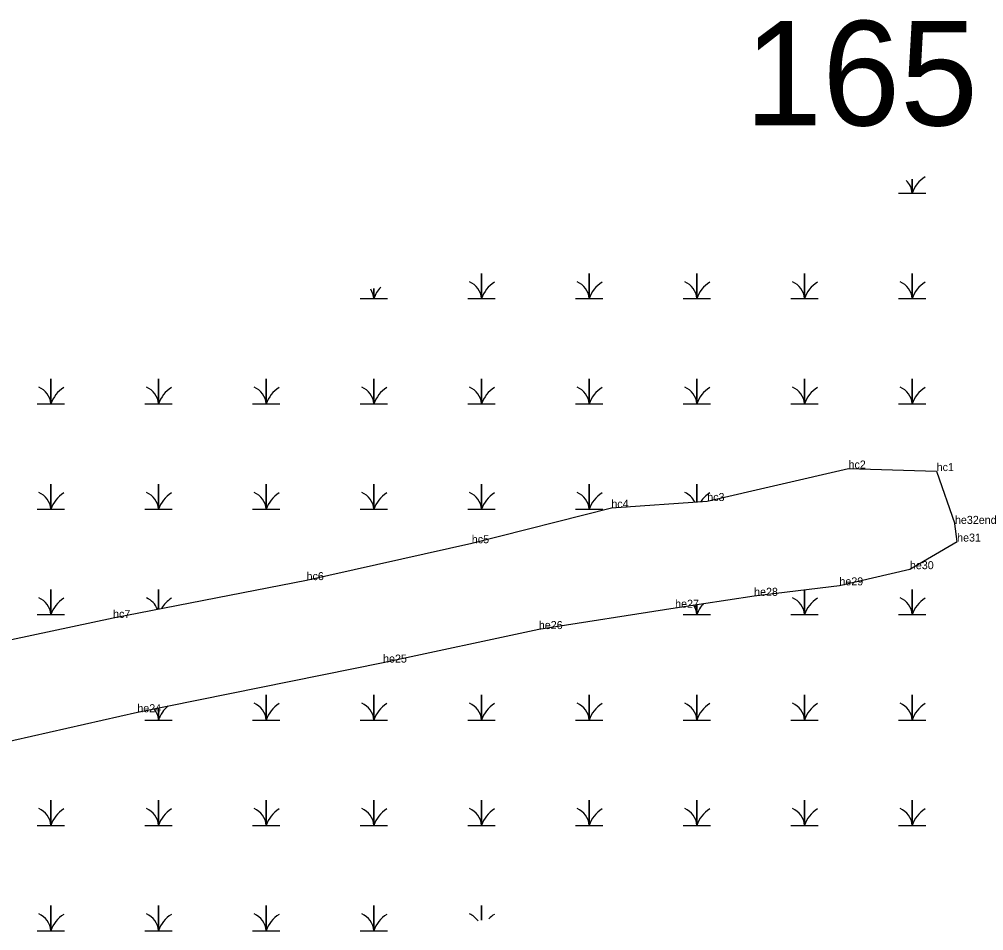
# Model space of a CAD drawing. Extents: x 2072529 to 2268796, y 436423 to 470406.
# Drawn here: x 2185430 to 2186032, y 453067 to 453636 of the extents above; entities that cross this region are included whole.
import ezdxf

# ---------------------------------------------------------------- set-up
doc = ezdxf.new("R2010")
doc.units = 0
for name, color, linetype in [('Default', 7, 'Continuous'), ('Exist Environmental Wetland Boundary', 7, 'Continuous'), ('Exist Environmental Wetland Boundary Cogo Comment', 7, 'Continuous'), ('Exist Hydro Swamp or Marsh', 7, 'Continuous'), ('Old_Level_20', 7, 'Continuous')]:
    doc.layers.add(name, color=color, linetype=linetype)

msp = doc.modelspace()

# ---------------------------------------------------------------- linework, layer by layer
at = {"layer": 'Exist Environmental Wetland Boundary'}
for points in [[(2185035.54, 453189.27), (2185047.47, 453170.42), (2185087.53, 453177.63), (2185090.05, 453198.25), (2185098.16, 453236.27), (2185126.21, 453250.87), (2185159.4, 453243.51), (2185177.54, 453239.84), (2185246.58, 453215.74), (2185332.93, 453229.41), (2185488.36, 453262.36), (2185609.23, 453285.97), (2185712.44, 453309.01), (2185799.6, 453331.13), (2185859.51, 453335.36), (2185947.74, 453355.65), (2186002.8, 453354.08), (2186014.23, 453321.09)], [(2185404.06, 453181.06), (2185503.52, 453203.47), (2185657.01, 453234.47), (2185754.31, 453255.41), (2185839.43, 453268.74), (2185888.76, 453276.18), (2185942.05, 453282.7), (2185986.08, 453292.81), (2186015.58, 453310.05), (2186014.23, 453321.09)]]:
    msp.add_lwpolyline(points, dxfattribs=at)
at = {"layer": 'Exist Hydro Swamp or Marsh'}
for points in [[(2185978.92, 453527.61), (2185987.52, 453527.61), (2185987.52, 453536.43)], [(2185987.52, 453536.43), (2185987.52, 453527.61), (2185996.12, 453527.61)], [(2185709.92, 453461.81), (2185718.52, 453461.81), (2185718.52, 453477.59), (2185718.52, 453461.81), (2185727.12, 453461.81)], [(2185777.17, 453461.81), (2185785.77, 453461.81), (2185785.77, 453477.59), (2185785.77, 453461.81), (2185794.37, 453461.81)], [(2185844.42, 453461.81), (2185853.02, 453461.81), (2185853.02, 453477.59), (2185853.02, 453461.81), (2185861.62, 453461.81)], [(2185911.67, 453461.81), (2185920.27, 453461.81), (2185920.27, 453477.59), (2185920.27, 453461.81), (2185928.87, 453461.81)], [(2185978.92, 453461.81), (2185987.52, 453461.81), (2185987.52, 453477.59), (2185987.52, 453461.81), (2185996.12, 453461.81)], [(2185642.67, 453461.81), (2185651.27, 453461.81), (2185651.27, 453468.06)], [(2185651.27, 453468.06), (2185651.27, 453461.81), (2185659.87, 453461.81)], [(2185440.92, 453396.01), (2185449.52, 453396.01), (2185449.52, 453411.79), (2185449.52, 453396.01), (2185458.12, 453396.01)], [(2185508.17, 453396.01), (2185516.77, 453396.01), (2185516.77, 453411.79), (2185516.77, 453396.01), (2185525.37, 453396.01)], [(2185575.42, 453396.01), (2185584.02, 453396.01), (2185584.02, 453411.79), (2185584.02, 453396.01), (2185592.62, 453396.01)], [(2185642.67, 453396.01), (2185651.27, 453396.01), (2185651.27, 453411.79), (2185651.27, 453396.01), (2185659.87, 453396.01)], [(2185709.92, 453396.01), (2185718.52, 453396.01), (2185718.52, 453411.79), (2185718.52, 453396.01), (2185727.12, 453396.01)], [(2185777.17, 453396.01), (2185785.77, 453396.01), (2185785.77, 453411.79), (2185785.77, 453396.01), (2185794.37, 453396.01)], [(2185844.42, 453396.01), (2185853.02, 453396.01), (2185853.02, 453411.79), (2185853.02, 453396.01), (2185861.62, 453396.01)], [(2185911.67, 453396.01), (2185920.27, 453396.01), (2185920.27, 453411.79), (2185920.27, 453396.01), (2185928.87, 453396.01)], [(2185978.92, 453396.01), (2185987.52, 453396.01), (2185987.52, 453411.79), (2185987.52, 453396.01), (2185996.12, 453396.01)], [(2185440.92, 453330.21), (2185449.52, 453330.21), (2185449.52, 453345.99), (2185449.52, 453330.21), (2185458.12, 453330.21)], [(2185508.17, 453330.21), (2185516.77, 453330.21), (2185516.77, 453345.99), (2185516.77, 453330.21), (2185525.37, 453330.21)], [(2185575.42, 453330.21), (2185584.02, 453330.21), (2185584.02, 453345.99), (2185584.02, 453330.21), (2185592.62, 453330.21)], [(2185642.67, 453330.21), (2185651.27, 453330.21), (2185651.27, 453345.99), (2185651.27, 453330.21), (2185659.87, 453330.21)], [(2185709.92, 453330.21), (2185718.52, 453330.21), (2185718.52, 453345.99), (2185718.52, 453330.21), (2185727.12, 453330.21)], [(2185777.17, 453330.21), (2185785.77, 453330.21), (2185785.77, 453345.99), (2185785.77, 453330.21), (2185794.37, 453330.21)], [(2185853.02, 453334.9), (2185853.02, 453345.99), (2185853.02, 453334.9)], [(2185440.92, 453264.41), (2185449.52, 453264.41), (2185449.52, 453280.19), (2185449.52, 453264.41), (2185458.12, 453264.41)], [(2185516.77, 453267.91), (2185516.77, 453280.19), (2185516.77, 453267.91)], [(2185911.67, 453264.41), (2185920.27, 453264.41), (2185920.27, 453280.03)], [(2185920.27, 453280.03), (2185920.27, 453264.41), (2185928.87, 453264.41)], [(2185978.92, 453264.41), (2185987.52, 453264.41), (2185987.52, 453280.19), (2185987.52, 453264.41), (2185996.12, 453264.41)], [(2185844.42, 453264.41), (2185853.02, 453264.41), (2185853.02, 453270.79)], [(2185853.02, 453270.79), (2185853.02, 453264.41), (2185861.62, 453264.41)], [(2185575.42, 453198.61), (2185584.02, 453198.61), (2185584.02, 453214.39), (2185584.02, 453198.61), (2185592.62, 453198.61)], [(2185642.67, 453198.61), (2185651.27, 453198.61), (2185651.27, 453214.39), (2185651.27, 453198.61), (2185659.87, 453198.61)], [(2185709.92, 453198.61), (2185718.52, 453198.61), (2185718.52, 453214.39), (2185718.52, 453198.61), (2185727.12, 453198.61)], [(2185777.17, 453198.61), (2185785.77, 453198.61), (2185785.77, 453214.39), (2185785.77, 453198.61), (2185794.37, 453198.61)], [(2185844.42, 453198.61), (2185853.02, 453198.61), (2185853.02, 453214.39), (2185853.02, 453198.61), (2185861.62, 453198.61)], [(2185911.67, 453198.61), (2185920.27, 453198.61), (2185920.27, 453214.39), (2185920.27, 453198.61), (2185928.87, 453198.61)], [(2185978.92, 453198.61), (2185987.52, 453198.61), (2185987.52, 453214.39), (2185987.52, 453198.61), (2185996.12, 453198.61)], [(2185508.17, 453198.61), (2185516.77, 453198.61), (2185516.77, 453206.15)], [(2185516.77, 453206.15), (2185516.77, 453198.61), (2185525.37, 453198.61)], [(2185440.92, 453132.81), (2185449.52, 453132.81), (2185449.52, 453148.59), (2185449.52, 453132.81), (2185458.12, 453132.81)], [(2185508.17, 453132.81), (2185516.77, 453132.81), (2185516.77, 453148.59), (2185516.77, 453132.81), (2185525.37, 453132.81)], [(2185575.42, 453132.81), (2185584.02, 453132.81), (2185584.02, 453148.59), (2185584.02, 453132.81), (2185592.62, 453132.81)], [(2185642.67, 453132.81), (2185651.27, 453132.81), (2185651.27, 453148.59), (2185651.27, 453132.81), (2185659.87, 453132.81)], [(2185709.92, 453132.81), (2185718.52, 453132.81), (2185718.52, 453148.59), (2185718.52, 453132.81), (2185727.12, 453132.81)], [(2185777.17, 453132.81), (2185785.77, 453132.81), (2185785.77, 453148.59), (2185785.77, 453132.81), (2185794.37, 453132.81)], [(2185844.42, 453132.81), (2185853.02, 453132.81), (2185853.02, 453148.59), (2185853.02, 453132.81), (2185861.62, 453132.81)], [(2185911.67, 453132.81), (2185920.27, 453132.81), (2185920.27, 453148.59), (2185920.27, 453132.81), (2185928.87, 453132.81)], [(2185978.92, 453132.81), (2185987.52, 453132.81), (2185987.52, 453148.59), (2185987.52, 453132.81), (2185996.12, 453132.81)], [(2185440.92, 453067.01), (2185449.52, 453067.01), (2185449.52, 453082.79), (2185449.52, 453067.01), (2185458.12, 453067.01)], [(2185508.17, 453067.01), (2185516.77, 453067.01), (2185516.77, 453082.79), (2185516.77, 453067.01), (2185525.37, 453067.01)], [(2185575.42, 453067.01), (2185584.02, 453067.01), (2185584.02, 453082.79), (2185584.02, 453067.01), (2185592.62, 453067.01)], [(2185642.67, 453067.01), (2185651.27, 453067.01), (2185651.27, 453082.79), (2185651.27, 453067.01), (2185659.87, 453067.01)], [(2185718.52, 453073.55), (2185718.52, 453082.79), (2185718.52, 453073.55)]]:
    msp.add_lwpolyline(points, dxfattribs=at)
for centre, radius, start, end in [((2185975.25, 453526.72), 12.3, 4.14034, 46.58619), ((2186005.76, 453521.55), 19.22, 122.12745, 161.62219), ((2185669.51, 453455.75), 19.22, 136.71945, 161.62219), ((2185706.25, 453460.92), 12.3, 4.14034, 67.53497), ((2185736.76, 453455.75), 19.22, 122.12745, 161.62219), ((2185773.5, 453460.92), 12.3, 4.14034, 67.53497), ((2185804.01, 453455.75), 19.22, 122.12745, 161.62219), ((2185840.75, 453460.92), 12.3, 4.14034, 67.53497), ((2185871.26, 453455.75), 19.22, 122.12745, 161.62219), ((2185908, 453460.92), 12.3, 4.14034, 67.53497), ((2185938.51, 453455.75), 19.22, 122.12745, 161.62219), ((2185975.25, 453460.92), 12.3, 4.14034, 67.53497), ((2186005.76, 453455.75), 19.22, 122.12745, 161.62219), ((2185639, 453460.92), 12.3, 4.14034, 33.23123), ((2185437.25, 453395.12), 12.3, 4.14034, 67.53497), ((2185467.76, 453389.95), 19.22, 122.12745, 161.62219), ((2185504.5, 453395.12), 12.3, 4.14034, 67.53497), ((2185535.01, 453389.95), 19.22, 122.12745, 161.62219), ((2185571.75, 453395.12), 12.3, 4.14034, 67.53497), ((2185602.26, 453389.95), 19.22, 122.12745, 161.62219), ((2185639, 453395.12), 12.3, 4.14034, 67.53497), ((2185669.51, 453389.95), 19.22, 122.12745, 161.62219), ((2185706.25, 453395.12), 12.3, 4.14034, 67.53497), ((2185736.76, 453389.95), 19.22, 122.12745, 161.62219), ((2185773.5, 453395.12), 12.3, 4.14034, 67.53497), ((2185804.01, 453389.95), 19.22, 122.12745, 161.62219), ((2185840.75, 453395.12), 12.3, 4.14034, 67.53497), ((2185871.26, 453389.95), 19.22, 122.12745, 161.62219), ((2185908, 453395.12), 12.3, 4.14034, 67.53497), ((2185938.51, 453389.95), 19.22, 122.12745, 161.62219), ((2185975.25, 453395.12), 12.3, 4.14034, 67.53497), ((2186005.76, 453389.95), 19.22, 122.12745, 161.62219), ((2185437.25, 453329.32), 12.3, 4.14034, 67.53497), ((2185467.76, 453324.15), 19.22, 122.12745, 161.62219), ((2185504.5, 453329.32), 12.3, 4.14034, 67.53497), ((2185535.01, 453324.15), 19.22, 122.12745, 161.62219), ((2185571.75, 453329.32), 12.3, 4.14034, 67.53497), ((2185602.26, 453324.15), 19.22, 122.12745, 161.62219), ((2185639, 453329.32), 12.3, 4.14034, 67.53497), ((2185669.51, 453324.15), 19.22, 122.12745, 161.62219), ((2185706.25, 453329.32), 12.3, 4.14034, 67.53497), ((2185736.76, 453324.15), 19.22, 122.12745, 161.62219), ((2185773.5, 453329.32), 12.3, 4.14034, 67.53497), ((2185804.01, 453324.15), 19.22, 122.12745, 161.62219), ((2185840.75, 453329.32), 12.3, 26.53508, 67.53497), ((2185871.26, 453324.15), 19.22, 122.12745, 145.35705), ((2185437.25, 453263.52), 12.3, 4.14034, 67.53497), ((2185467.76, 453258.35), 19.22, 122.12745, 161.62219), ((2185504.5, 453263.52), 12.3, 20.20888, 67.53497), ((2185535.01, 453258.35), 19.22, 122.12745, 148.97226), ((2185840.75, 453263.52), 12.3, 4.14034, 34.42256), ((2185871.26, 453258.35), 19.22, 137.16238, 161.62219), ((2185908, 453263.52), 12.3, 4.14034, 67.53497), ((2185938.51, 453258.35), 19.22, 122.12745, 161.62219), ((2185975.25, 453263.52), 12.3, 4.14034, 67.53497), ((2186005.76, 453258.35), 19.22, 122.12745, 161.62219), ((2185571.75, 453197.72), 12.3, 4.14034, 67.53497), ((2185639, 453197.72), 12.3, 4.14034, 67.53497), ((2185706.25, 453197.72), 12.3, 4.14034, 67.53497), ((2185773.5, 453197.72), 12.3, 4.14034, 67.53497), ((2185840.75, 453197.72), 12.3, 4.14034, 67.53497), ((2185908, 453197.72), 12.3, 4.14034, 67.53497), ((2185975.25, 453197.72), 12.3, 4.14034, 67.53497), ((2185504.5, 453197.72), 12.3, 4.14034, 39.74963), ((2185535.01, 453192.55), 19.22, 129.58465, 161.62219), ((2185602.26, 453192.55), 19.22, 122.12745, 161.62219), ((2185669.51, 453192.55), 19.22, 122.12745, 161.62219), ((2185736.76, 453192.55), 19.22, 122.12745, 161.62219), ((2185804.01, 453192.55), 19.22, 122.12745, 161.62219), ((2185871.26, 453192.55), 19.22, 122.12745, 161.62219), ((2185938.51, 453192.55), 19.22, 122.12745, 161.62219), ((2186005.76, 453192.55), 19.22, 122.12745, 161.62219), ((2185437.25, 453131.92), 12.3, 4.14034, 67.53497), ((2185467.76, 453126.75), 19.22, 122.12745, 161.62219), ((2185504.5, 453131.92), 12.3, 4.14034, 67.53497), ((2185535.01, 453126.75), 19.22, 122.12745, 161.62219), ((2185571.75, 453131.92), 12.3, 4.14034, 67.53497), ((2185602.26, 453126.75), 19.22, 122.12745, 161.62219), ((2185639, 453131.92), 12.3, 4.14034, 67.53497), ((2185669.51, 453126.75), 19.22, 122.12745, 161.62219), ((2185706.25, 453131.92), 12.3, 4.14034, 67.53497), ((2185736.76, 453126.75), 19.22, 122.12745, 161.62219), ((2185773.5, 453131.92), 12.3, 4.14034, 67.53497), ((2185804.01, 453126.75), 19.22, 122.12745, 161.62219), ((2185840.75, 453131.92), 12.3, 4.14034, 67.53497), ((2185871.26, 453126.75), 19.22, 122.12745, 161.62219), ((2185908, 453131.92), 12.3, 4.14034, 67.53497), ((2185938.51, 453126.75), 19.22, 122.12745, 161.62219), ((2185975.25, 453131.92), 12.3, 4.14034, 67.53497), ((2186005.76, 453126.75), 19.22, 122.12745, 161.62219), ((2185437.25, 453066.12), 12.3, 4.14034, 67.53497), ((2185467.76, 453060.95), 19.22, 122.12745, 161.62219), ((2185504.5, 453066.12), 12.3, 4.14034, 67.53497), ((2185535.01, 453060.95), 19.22, 122.12745, 161.62219), ((2185571.75, 453066.12), 12.3, 4.14034, 67.53497), ((2185602.26, 453060.95), 19.22, 122.12745, 161.62219), ((2185639, 453066.12), 12.3, 4.14034, 67.53497), ((2185669.51, 453060.95), 19.22, 122.12745, 161.62219), ((2185706.25, 453066.12), 12.3, 34.65888, 67.53497), ((2185736.76, 453060.95), 19.22, 122.12745, 135.22837)]:
    msp.add_arc(centre, radius, start, end, dxfattribs=at)
at = {"layer": 'Old_Level_20'}
for p, q in [((2185947.74, 453355.65), (2185947.74, 453355.65)), ((2186002.8, 453354.08), (2186002.8, 453354.08)), ((2185799.6, 453331.13), (2185799.6, 453331.13)), ((2185859.51, 453335.36), (2185859.51, 453335.36)), ((2186014.23, 453321.09), (2186014.23, 453321.09)), ((2185712.44, 453309.01), (2185712.44, 453309.01)), ((2186015.58, 453310.05), (2186015.58, 453310.05)), ((2185986.08, 453292.81), (2185986.08, 453292.81)), ((2185609.23, 453285.97), (2185609.23, 453285.97)), ((2185942.05, 453282.7), (2185942.05, 453282.7)), ((2185888.76, 453276.18), (2185888.76, 453276.18)), ((2185839.43, 453268.74), (2185839.43, 453268.74)), ((2185488.36, 453262.36), (2185488.36, 453262.36)), ((2185754.31, 453255.41), (2185754.31, 453255.41)), ((2185657.01, 453234.47), (2185657.01, 453234.47)), ((2185503.52, 453203.47), (2185503.52, 453203.47))]:
    msp.add_line(p, q, dxfattribs=at)

# ---------------------------------------------------------------- texts
at = {"layer": 'Default'}
msp.add_text('165', height=65.34, dxfattribs=at).set_placement((2185882.79, 453569.95))
at = {"layer": 'Exist Environmental Wetland Boundary Cogo Comment'}
for s, p in [('hc2', (2185947.74, 453355.65)), ('hc1', (2186002.8, 453354.08)), ('hc4', (2185799.6, 453331.13)), ('hc3', (2185859.51, 453335.36)), ('he32end', (2186014.23, 453321.09)), ('hc5', (2185712.44, 453309.01)), ('he31', (2186015.58, 453310.05)), ('he30', (2185986.08, 453292.81)), ('hc6', (2185609.23, 453285.97)), ('he29', (2185942.05, 453282.7)), ('he28', (2185888.76, 453276.18)), ('he27', (2185839.43, 453268.74)), ('hc7', (2185488.36, 453262.36)), ('he26', (2185754.31, 453255.41)), ('he25', (2185657.01, 453234.47)), ('he24', (2185503.52, 453203.47))]:
    msp.add_text(s, height=5, dxfattribs=at).set_placement(p)

doc.saveas('drawing.dxf')
